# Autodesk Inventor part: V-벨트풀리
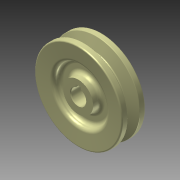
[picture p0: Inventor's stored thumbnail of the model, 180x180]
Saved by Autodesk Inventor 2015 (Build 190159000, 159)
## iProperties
Created: 2016-08
Part Number: V-벨트풀리
Material: 일반
Document SubType Name: Modeling
Designer: mduedu
Density: 1 g/cm^3
Mass: 44.0848 g
Surface Area: 158.218 cm^2
Volume: 44.0848 cm^3
Appearance: 알루미늄 - 평지
Author: mduedu
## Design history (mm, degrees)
sketch "스케치1"
  geometry: L1 (0, 9.5)-(0, -9.5); L2 (0, 9.5)-(35, 9.5); L3 (35, 9.5)-(35, 4.825); L4 (35, 4.825)-(26, 2.074); L5 (26, 2.074)-(26, 0); L6 (0, 0)-(26, 0); L7 (0, -9.5)-(35, -9.5); L8 (35, -9.5)-(35, -4.825); L9 (35, -4.825)-(26, -2.074); L10 (26, -2.074)-(26, 0); L11 (32.3, 9.5)-(32.3, -9.5); 3 further points
  constraints: 22 end point, 6 point on line, 4 perpendicular, 3 symmetric about line, 1 coincident, 1 horizontal alignment, 1 midpoint, 1 parallel, 1 vertical
  dimensions: "d0" = 19 distance of L1.start L1.end; "d2" = 70 diameter of L8 L1; "d4" = 6.3 distance between parallel lines of L10 L11; "d5" = 2.7 distance between parallel lines of L11 L8; "d6" = 8 distance of point (32.3, -4) point (32.3, 4); "d7" = 34 deg angle of L9 L4
revolve "회전1" sketch "스케치1" stored, may be unused: angle "d8" = 90 deg
sketch "스케치2"
  geometry: L1 (-2, 0)-(2, 0); L2 (2, 0)-(2, 7.8); L3 (2, 7.8)-(-2, 7.8); L4 (-2, 7.8)-(-2, 0); C1 r 6 at (0, 0); 2 further points
  constraints: 8 end point, 2 coincident, 2 parallel, 1 centre point, 1 horizontal, 1 midpoint, 1 perpendicular
  dimensions: "d9" = 12 diameter of C1; "d11" = 4 distance of L2.end L3.end; "d12" = 7.8 distance of L1.end L2.end
extrude "돌출1" cut sketch "스케치2" stored distance "d13" = 10; taper "d14" = 0 deg
sketch "스케치3"
  geometry: L1 (35, 4.825)-(26, 2.074) reference; L2 (26, 2.074)-(26, -2.074) reference; L3 (0, 0)-(26, 0); L4 (35, 9.5)-(35, 4.825) reference; L5 (-35, 9.5)-(35, 9.5) reference; L6 (35, 9.5)-(21, 8.275); L7 (21, 8.275)-(21, 3); L8 (21, 3)-(12, 3); L9 (12, 3)-(12, 9.5); L10 (0, 9.5)-(0, -9.5); L11 (5.657, -9.5)-(-6, -9.5) reference; L12 (12, 9.5)-(35, 9.5)
  constraints: 14 end point, 3 midpoint, 2 perpendicular, 2 point on line, 1 collinear, 1 horizontal, 1 parallel
  dimensions: "d15" = 3 distance between parallel lines of L3 L8; "d17" = 42 diameter of L7 L10; "d18" = 24 diameter of L9 L10; "d31" = 5 deg angle of L6 L5
revolve "회전2" sketch "스케치3" stored, may be unused: angle "d19" = 90 deg
fillet "모깎기1" dims "d20" = 0.5, "d21" = 1, "d22" = 1
fillet "모깎기2" dims "d23" = 3
fillet "모깎기3" dims "d24" = 3
fillet "모깎기4" dims "d25" = 3
chamfer "모따기1" distance "d26" = 0.5; stored, may be unused: second distance "d27" = 2, angle "d28" = 45 deg
node "솔리드1"
mirror "대칭1"
